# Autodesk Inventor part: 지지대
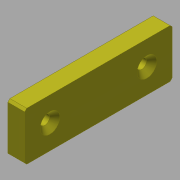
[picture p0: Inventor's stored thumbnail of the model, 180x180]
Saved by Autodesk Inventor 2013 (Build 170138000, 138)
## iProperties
Created: 2017-04
Part Number: 지지대
Material: 강철
Document SubType Name: Modeling
Designer: mduedu
Density: 1 g/cm^3
Author: mduedu
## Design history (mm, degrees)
sketch "스케치1"
  geometry: L1 (23, -35)-(23, 35); L2 (0, -35)-(0, 35); L3 (0, 35)-(23, 35); L4 (0, -35)-(23, -35); 2 further points
  constraints: 8 end point, 2 parallel, 1 coincident, 1 midpoint, 1 perpendicular, 1 vertical
  dimensions: "d1" = 23 distance between parallel lines of L2 L1; "d15" = 70 distance of L1.start L1.end
extrude "돌출1" new body sketch "스케치1" distance "d2" = 8; taper "d3" = 0 deg
chamfer "모따기2" distance "d16" = 1; stored, may be unused: second distance "d17" = 2, angle "d18" = 45 deg
sketch "스케치2"
  geometry: L1 (1, -35)-(22, -35) reference; L2 (23, -34)-(23, 34) reference; L3 (22, 35)-(1, 35) reference; L4 (0, 34)-(0, -34) reference; L5 (11.5, 35)-(11.5, -35); L6 (23, 0)-(0, 0); L7 (1, -35)-(0, -34) reference; L8 (23, -34)-(22, -35) reference; L9 (22, 35)-(23, 34) reference; L10 (0, 34)-(1, 35) reference; 2 further points
  constraints: 4 end point, 4 midpoint, 1 point on line, 1 symmetric about line
  dimensions: "d7" = 12 distance from line of point (11.5, 23) L3
  node "투영된 루프1"
sketch "스케치3"
  geometry: 4 further points
  constraints: 2 coincident
hole "구멍1" sketch "스케치3" at (11.5, 23), (11.5, -23) diameter "d8" = 4.5; stored, may be unused: countersink angle "d12" = 90 deg, drill point angle "d14" = 0 deg; dims "d9" = 6, "d10" = 9.4, "d11" = 2, "d13" = 8
node "솔리드2"
node "솔리드1"
